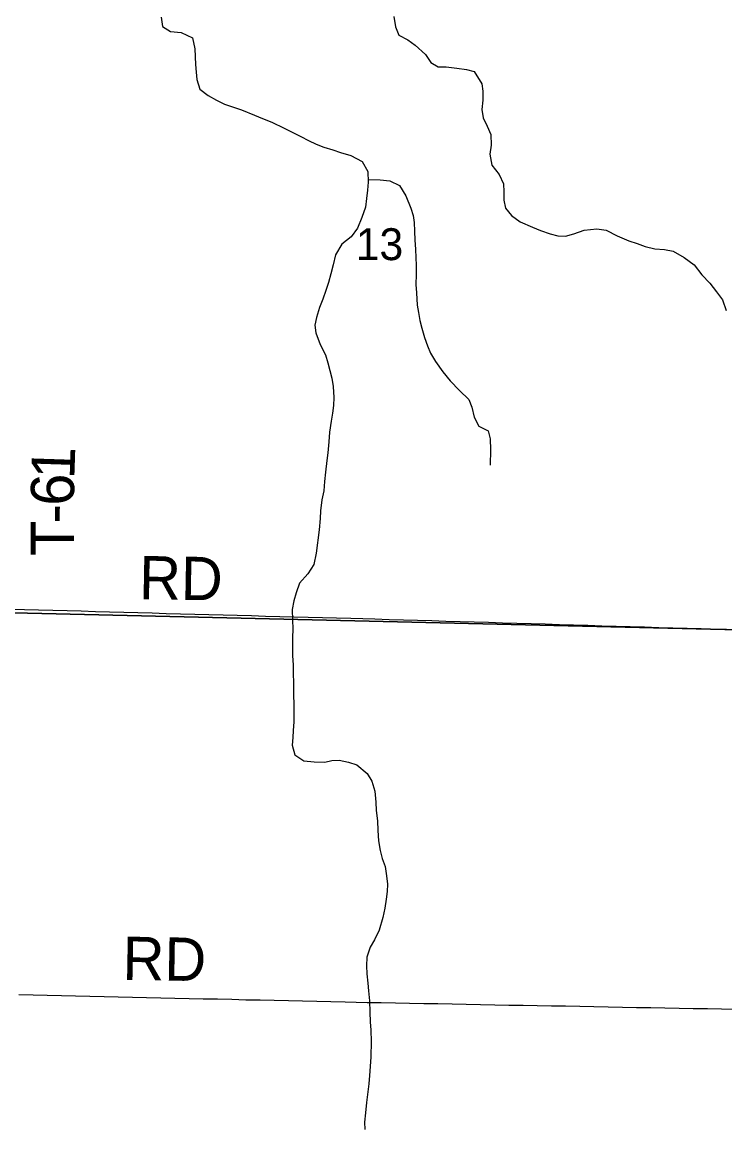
# Model space of a CAD drawing. Extents: x 0 to 34, y 0 to 22.
# Drawn here: x 6.802 to 7.725, y 15.728 to 17.185 of the extents above; entities that cross this region are included whole.
import ezdxf

# ---------------------------------------------------------------- set-up
doc = ezdxf.new("R2010")
doc.units = 0
for name, color, linetype in [('GM_X_Corporation', 7, 'Continuous'), ('GM_X_County_Road', 7, 'Continuous'), ('GM_X_County_Road_Text', 7, 'Continuous'), ('GM_X_Minor_River', 7, 'Continuous'), ('GM_X_Section_Text', 7, 'Continuous'), ('GM_X_Township_Road_Text', 7, 'Continuous')]:
    doc.layers.add(name, color=color, linetype=linetype)

msp = doc.modelspace()

# ---------------------------------------------------------------- linework, layer by layer
at = {"layer": 'GM_X_Corporation'}
for points in [[(6.7715, 16.4096), (7.7624, 16.3866)], [(7.7505, 15.7051), (7.751, 15.7381), (7.7516, 15.7672), (7.7522, 15.802), (7.7529, 15.8449), (7.7534, 15.889), (7.7535, 15.894), (7.7537, 15.9122), (7.7538, 15.9164), (7.7541, 15.9412), (7.7549, 15.9779), (7.7552, 15.9922), (7.7559, 16.0301), (7.7566, 16.0661), (7.7574, 16.1171), (7.7587, 16.173), (7.7599, 16.2314), (7.7606, 16.278), (7.7613, 16.3153), (7.7623, 16.3643), (7.7624, 16.3866), (6.7715, 16.4096)]]:
    msp.add_lwpolyline(points, dxfattribs=at)
at = {"layer": 'GM_X_County_Road'}
for points in [[(6.7866, 16.4142), (6.8053, 16.4137), (6.8239, 16.4132), (6.8425, 16.4127), (6.8612, 16.4122), (6.8798, 16.4117), (6.8984, 16.4111), (6.9171, 16.4106), (6.9357, 16.4101), (6.9543, 16.4096), (6.973, 16.4091), (6.9916, 16.4086), (7.0102, 16.4081), (7.0289, 16.4076), (7.0475, 16.4071), (7.0661, 16.4066), (7.0848, 16.4061), (7.1034, 16.4056), (7.122, 16.4051), (7.1407, 16.4046), (7.1593, 16.4041), (7.1779, 16.4036), (7.1966, 16.4031), (7.2152, 16.4026), (7.2339, 16.4021), (7.2498, 16.4017), (7.2657, 16.4013), (7.2843, 16.4007), (7.303, 16.4002), (7.3216, 16.3996), (7.3402, 16.3991), (7.3589, 16.3985), (7.3775, 16.398), (7.3961, 16.3974), (7.4148, 16.3969), (7.4334, 16.3963), (7.4521, 16.3958), (7.4707, 16.3952), (7.4893, 16.3946), (7.508, 16.3941), (7.5266, 16.3935), (7.5452, 16.393), (7.5639, 16.3924), (7.5825, 16.3919), (7.6011, 16.3913), (7.6198, 16.3908), (7.6384, 16.3902), (7.657, 16.3897), (7.6757, 16.3891), (7.6943, 16.3886), (7.7129, 16.388), (7.7275, 16.3876)], [(6.798, 15.9079), (6.8166, 15.9074), (6.8353, 15.907), (6.8539, 15.9066), (6.8725, 15.9062), (6.8912, 15.9058), (6.9098, 15.9054), (6.9284, 15.905), (6.9471, 15.9045), (6.9657, 15.9041), (6.9843, 15.9037), (7.003, 15.9033), (7.0216, 15.9029), (7.0402, 15.9025), (7.0589, 15.9021), (7.0775, 15.9017), (7.0961, 15.9012), (7.1148, 15.9008), (7.1334, 15.9004), (7.152, 15.9), (7.1707, 15.8996), (7.1893, 15.8992), (7.2079, 15.8988), (7.2266, 15.8983), (7.2409, 15.898), (7.2553, 15.8977), (7.2739, 15.8974), (7.2925, 15.897), (7.3112, 15.8967), (7.3298, 15.8963), (7.3484, 15.896), (7.3671, 15.8956), (7.3857, 15.8953), (7.4043, 15.8949), (7.423, 15.8946), (7.4416, 15.8942), (7.4603, 15.8939), (7.4789, 15.8935), (7.4975, 15.8932), (7.5162, 15.8929), (7.5348, 15.8925), (7.5534, 15.8922), (7.5721, 15.8918), (7.5907, 15.8915), (7.6093, 15.8911), (7.628, 15.8908), (7.6466, 15.8904), (7.6652, 15.8901), (7.6839, 15.8898), (7.7025, 15.8894), (7.7211, 15.8891), (7.7374, 15.8888)]]:
    msp.add_lwpolyline(points, dxfattribs=at)
at = {"layer": 'GM_X_Minor_River'}
for points in [[(6.9849, 17.1915), (6.9865, 17.1792), (6.9973, 17.1729), (7.0109, 17.1714), (7.0259, 17.1645), (7.029, 17.15), (7.03, 17.1295), (7.0308, 17.1192), (7.0317, 17.1096), (7.0356, 17.097), (7.0464, 17.0887), (7.0576, 17.0824), (7.0681, 17.0775), (7.0786, 17.0738), (7.0903, 17.0697), (7.1076, 17.0628), (7.1181, 17.0584), (7.1301, 17.0535), (7.1462, 17.0458), (7.1586, 17.0398), (7.1683, 17.035), (7.1784, 17.0294), (7.1885, 17.0246)], [(7.2907, 17.1926), (7.2926, 17.1789), (7.2969, 17.1678), (7.3089, 17.1618), (7.3186, 17.1547), (7.3319, 17.1425), (7.3392, 17.1321), (7.3489, 17.1265), (7.3592, 17.1262), (7.3732, 17.1247), (7.386, 17.1229), (7.3958, 17.1203), (7.406, 17.1041), (7.4073, 17.0946), (7.4074, 17.0824)], [(7.4074, 17.0824), (7.4063, 17.0703), (7.4079, 17.0596), (7.4133, 17.0484), (7.418, 17.0377), (7.4184, 17.0236), (7.4165, 17.0115), (7.4192, 16.9973), (7.4288, 16.9849), (7.4345, 16.9726), (7.435, 16.962), (7.4351, 16.9513), (7.4371, 16.9406), (7.4452, 16.9309), (7.4564, 16.923), (7.4725, 16.9158), (7.483, 16.9113), (7.4958, 16.9072), (7.506, 16.9043), (7.5158, 16.904), (7.5269, 16.9071), (7.5403, 16.9117), (7.557, 16.9136), (7.5695, 16.9117), (7.5837, 16.9042), (7.5991, 16.8977), (7.61, 16.8944), (7.6205, 16.8903), (7.6334, 16.8873), (7.6462, 16.8866), (7.6576, 16.8844), (7.6718, 16.876), (7.6848, 16.8662), (7.6951, 16.8534), (7.7058, 16.8421), (7.7142, 16.8309), (7.7223, 16.8204), (7.7272, 16.8062)], [(7.1885, 17.0246), (7.1987, 17.0209), (7.2103, 17.0172), (7.2205, 17.0139), (7.234, 17.0097), (7.249, 17.0021), (7.2563, 16.989), (7.2567, 16.9749), (7.256, 16.9643), (7.2546, 16.9533), (7.2531, 16.942), (7.2486, 16.9284), (7.2426, 16.9145), (7.2343, 16.9029), (7.2223, 16.8934), (7.214, 16.8795), (7.211, 16.8663), (7.2076, 16.8546), (7.2047, 16.8433), (7.201, 16.8327), (7.1973, 16.8214), (7.1929, 16.8105), (7.1887, 16.7973), (7.1869, 16.7871), (7.1882, 16.7768), (7.1935, 16.7619), (7.2007, 16.748), (7.2039, 16.7376), (7.2066, 16.7277), (7.209, 16.7174), (7.2107, 16.7067), (7.2118, 16.6922), (7.2111, 16.6816), (7.2101, 16.6714), (7.2083, 16.6608), (7.2061, 16.6464), (7.205, 16.6339), (7.2038, 16.6195), (7.2024, 16.6093), (7.2009, 16.5941), (7.1994, 16.5816), (7.1984, 16.5695), (7.1958, 16.5578), (7.1943, 16.5434), (7.1936, 16.5331), (7.1925, 16.5183), (7.1883, 16.4877), (7.1852, 16.4726), (7.1777, 16.4606), (7.1664, 16.4484), (7.1623, 16.4356), (7.1589, 16.425), (7.1571, 16.4137), (7.1575, 16.3996), (7.1576, 16.3882), (7.1573, 16.3764), (7.1574, 16.3643), (7.1574, 16.3533), (7.1583, 16.3407), (7.1584, 16.3301), (7.1588, 16.3168), (7.1588, 16.3016), (7.1592, 16.289), (7.1593, 16.2776), (7.159, 16.2659), (7.1583, 16.2549), (7.1577, 16.2454), (7.157, 16.2355), (7.1605, 16.2229), (7.1724, 16.215), (7.1857, 16.2135), (7.1997, 16.2132), (7.2092, 16.2152), (7.2187, 16.2157), (7.2308, 16.2131), (7.2417, 16.2098), (7.2554, 16.1984), (7.2616, 16.188), (7.2654, 16.175), (7.267, 16.1605), (7.2674, 16.1495), (7.269, 16.1362), (7.2694, 16.1233), (7.2702, 16.11), (7.2725, 16.097), (7.2753, 16.0867), (7.2792, 16.0763), (7.2807, 16.0637), (7.282, 16.0531), (7.2817, 16.0432), (7.2803, 16.0334), (7.2785, 16.0213), (7.2759, 16.0092), (7.2713, 15.9926), (7.2653, 15.9799), (7.2593, 15.9701), (7.2552, 15.957), (7.2545, 15.9456), (7.255, 15.9353), (7.2562, 15.9228), (7.257, 15.9129)], [(7.2566, 16.9782), (7.2727, 16.978), (7.2851, 16.9765), (7.2979, 16.9705), (7.3063, 16.9569), (7.3127, 16.9408), (7.3158, 16.9312), (7.3171, 16.9217), (7.3176, 16.9107), (7.318, 16.8989), (7.3189, 16.8867), (7.3193, 16.8756), (7.3198, 16.8658), (7.3199, 16.8536), (7.3196, 16.8407), (7.3201, 16.8296), (7.3211, 16.8133), (7.3228, 16.8037), (7.3248, 16.793), (7.3272, 16.7831), (7.3307, 16.7708), (7.3349, 16.7601), (7.3385, 16.7501), (7.345, 16.7393), (7.3549, 16.7258), (7.3645, 16.7141), (7.3767, 16.7013), (7.3889, 16.6895), (7.3928, 16.6796), (7.3959, 16.6662), (7.402, 16.6546), (7.4144, 16.6482), (7.4171, 16.6379), (7.4175, 16.6235), (7.417, 16.603)], [(7.257, 15.9129), (7.2586, 15.8995), (7.259, 15.8847), (7.2594, 15.8722), (7.2602, 15.8612), (7.2606, 15.8463), (7.2601, 15.8262), (7.2594, 15.8133), (7.2587, 15.8016), (7.2576, 15.7906), (7.2557, 15.7766), (7.2547, 15.766), (7.2532, 15.7524), (7.2521, 15.7403), (7.2526, 15.7308)]]:
    msp.add_lwpolyline(points, dxfattribs=at)

# ---------------------------------------------------------------- texts
at = {"layer": 'GM_X_County_Road_Text'}
for rotation, p in [(359.0118, (6.9555, 16.4273)), (359.0128, (6.9338, 15.9273))]:
    msp.add_text('RD', height=0.05682, rotation=rotation, dxfattribs=at).set_placement(p)
at = {"layer": 'GM_X_Section_Text'}
msp.add_text('13', height=0.04186, rotation=0, dxfattribs=at).set_placement((7.2405, 16.8725))
at = {"layer": 'GM_X_Township_Road_Text'}
for s, rotation, p in [('1', 88.1288, (6.8707, 16.5844)), ('6', 89.6253, (6.8704, 16.5498)), ('-', 89.9219, (6.8704, 16.5266)), ('T', 89.9936, (6.8704, 16.4841))]:
    msp.add_text(s, height=0.0568, rotation=rotation, dxfattribs=at).set_placement(p)

doc.saveas('drawing.dxf')
